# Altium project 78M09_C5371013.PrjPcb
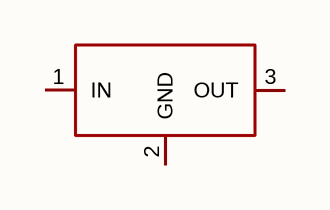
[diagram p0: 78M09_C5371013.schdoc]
1 sheet, 1 parts. Net scope: global (net labels, ports and power ports of the same name join across sheets).

## Sheet 78M09_C5371013.schdoc
size 127 x 101 mm

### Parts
U?  78m09_c5371013  [TO-252-3_L6.6-W6.1-P4.57-LS9.9-BR-CW]  (value not drawn)

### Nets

Not connected (* = marked no-connect by the designer): U? 1(IN) 2(GND) 3(OUT)

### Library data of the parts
U? = 78m09_c5371013: 输出极性:正极;工作电压:35V;输出电压:9V;输出电流:500mA;电源纹波抑制比(PSRR):56dB@(120Hz);输出类型:固定;; Manufacturer: TECH PUBLIC(台舟); ManufacturerPart: 78M09; AddInBom: yes; ModelId: dee852f3c6b348a2b9d5be5dd3244081; ModelTransform: 258.97184,390.1567,0,90,0,0,-35.433,0,0; Output Configuration: 正极; Voltage - Supply: 35V; Output Voltage: 9V; Output Current: 500mA; Voltage Dropout: 2V@(350mA); standby current: 6mA; Noise: 58uV; Output Type: 固定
